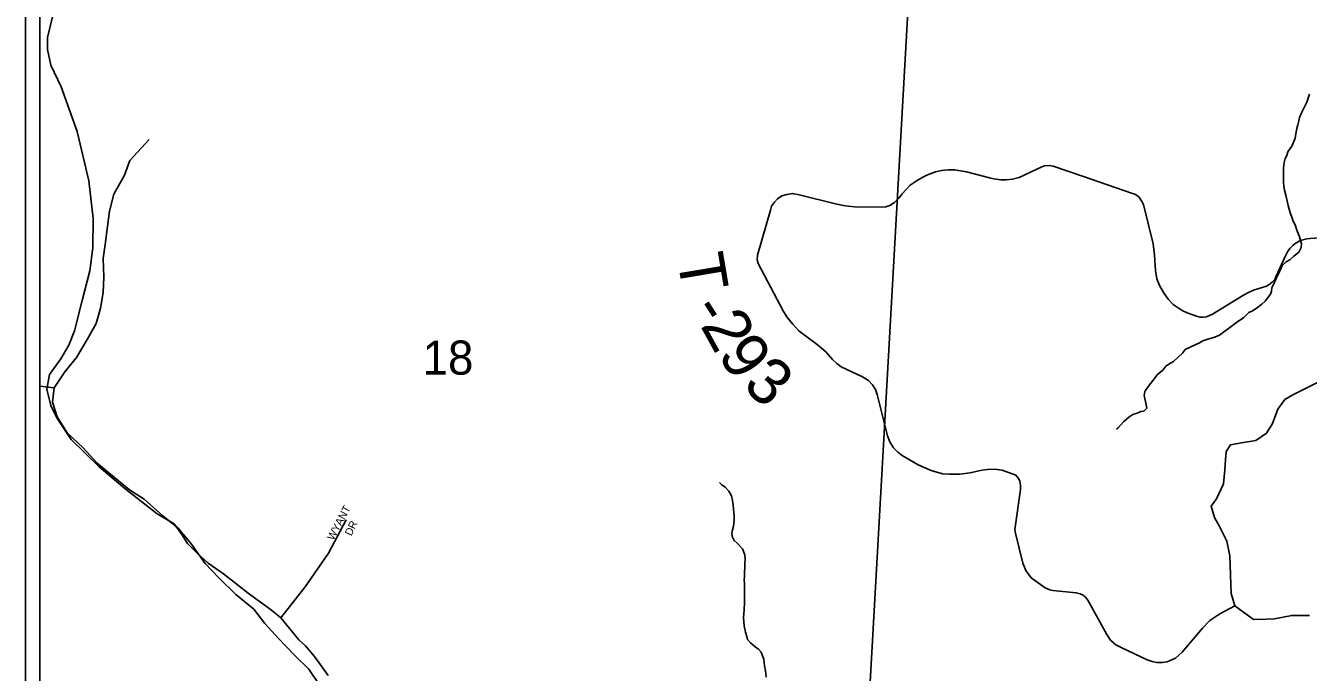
# Model space of a CAD drawing. Extents: x 0 to 34, y 0 to 22.
# Drawn here: x 2.6 to 4.174, y 18.251 to 19.045 of the extents above; entities that cross this region are included whole.
import ezdxf

# ---------------------------------------------------------------- set-up
doc = ezdxf.new("R2010")
doc.units = 0
for name, color, linetype in [('GM_X_County', 7, 'Continuous'), ('GM_X_County_Road', 7, 'Continuous'), ('GM_X_Minor_River', 7, 'Continuous'), ('GM_X_Section', 7, 'Continuous'), ('GM_X_Section_Text', 7, 'Continuous'), ('GM_X_Township', 7, 'Continuous'), ('GM_X_Township_Road', 7, 'Continuous'), ('GM_X_Township_Road_Text', 7, 'Continuous'), ('GM_X_Township_ROW', 7, 'Continuous'), ('GM_X_Township_Subdivision', 7, 'Continuous'), ('GM_X_Township_Subdivision_Text', 7, 'Continuous'), ('SH_Data', 7, 'Continuous')]:
    doc.layers.add(name, color=color, linetype=linetype)

msp = doc.modelspace()

# ---------------------------------------------------------------- linework, layer by layer
at = {"layer": 'GM_X_County'}
msp.add_lwpolyline([(9.4175, 16.6203), (9.4175, 20.9), (2.6175, 20.9), (2.6175, 15.1694)], dxfattribs=at)
at = {"layer": 'GM_X_County_Road'}
for points in [[(2.9713, 18.2478), (2.9542, 18.2709), (2.9432, 18.2841), (2.9352, 18.2913), (2.9132, 18.3182), (2.9014, 18.3277), (2.8729, 18.3485), (2.8429, 18.3723), (2.8239, 18.3856), (2.8095, 18.3984), (2.7985, 18.4098), (2.7916, 18.4208), (2.7821, 18.4337), (2.7612, 18.4461), (2.7217, 18.4772), (2.6902, 18.5036), (2.656, 18.5373), (2.6381, 18.5639), (2.6309, 18.579), (2.6259, 18.5991), (2.6293, 18.6169), (2.6433, 18.6363), (2.6531, 18.653), (2.6599, 18.6705), (2.6692, 18.7077), (2.6786, 18.7441), (2.6824, 18.7726), (2.683, 18.8086), (2.6776, 18.8545), (2.6631, 18.9152), (2.6436, 18.9698), (2.6307, 18.9967), (2.6268, 19.0157), (2.6268, 19.0305), (2.6362, 19.0696)], [(4.1752, 18.3214), (4.1686, 18.3214), (4.1533, 18.3214), (4.1322, 18.3173), (4.1222, 18.3168), (4.1065, 18.3165), (4.0833, 18.3329), (4.0791, 18.3484), (4.0779, 18.3712), (4.0774, 18.3944), (4.0736, 18.4126), (4.0641, 18.4311), (4.0584, 18.4414), (4.0542, 18.4554), (4.061, 18.4645), (4.0696, 18.4828), (4.0711, 18.4998), (4.0718, 18.5124), (4.0726, 18.5226), (4.0779, 18.5306), (4.0915, 18.5333), (4.1093, 18.536), (4.1222, 18.5451), (4.1297, 18.5569), (4.1361, 18.5743), (4.1448, 18.5865), (4.1547, 18.5922), (4.1872, 18.6082)]]:
    msp.add_lwpolyline(points, dxfattribs=at)
at = {"layer": 'GM_X_Minor_River'}
for points in [[(4.1752, 18.9609), (4.1716, 18.951), (4.1697, 18.9469), (4.1657, 18.939), (4.1626, 18.9322), (4.1618, 18.9284), (4.1606, 18.9235), (4.1593, 18.919), (4.1585, 18.9148), (4.1576, 18.9072), (4.1537, 18.8982), (4.1513, 18.8944), (4.1486, 18.8903), (4.1474, 18.8858), (4.145, 18.882), (4.1438, 18.8771), (4.1433, 18.8706), (4.143, 18.8536), (4.1437, 18.8475), (4.1444, 18.8433), (4.1465, 18.8356), (4.149, 18.8242), (4.1514, 18.8154), (4.1529, 18.8112), (4.1551, 18.8051), (4.1576, 18.8005), (4.1594, 18.794), (4.1627, 18.786), (4.1641, 18.7814), (4.1652, 18.7776), (4.1647, 18.7727), (4.162, 18.767), (4.1558, 18.7622), (4.1508, 18.7577), (4.1462, 18.7551), (4.1416, 18.7507), (4.1392, 18.745), (4.1365, 18.7397), (4.1341, 18.7348), (4.1313, 18.7281), (4.129, 18.7235), (4.1285, 18.7194), (4.127, 18.7156), (4.1207, 18.707), (4.1165, 18.7032), (4.1096, 18.6981), (4.105, 18.6951), (4.1004, 18.6929), (4.0943, 18.6869), (4.0854, 18.681), (4.0774, 18.6747), (4.0712, 18.6702), (4.0647, 18.6654), (4.059, 18.6628), (4.0514, 18.6607), (4.0441, 18.6582), (4.0399, 18.6559), (4.0288, 18.6504), (4.0224, 18.6475), (4.0196, 18.6434), (4.0081, 18.6329), (4.0043, 18.6307), (3.9989, 18.6274), (3.995, 18.6225), (3.9885, 18.617), (3.9834, 18.6102), (3.9776, 18.6027), (3.973, 18.596), (3.9721, 18.5914), (3.9732, 18.5876)], [(2.7514, 18.9055), (2.7279, 18.8798), (2.7211, 18.8616), (2.7081, 18.8381), (2.7028, 18.8176), (2.7005, 18.7986), (2.6974, 18.7766), (2.6951, 18.7592), (2.6959, 18.7364), (2.6951, 18.7175), (2.692, 18.6985), (2.6867, 18.6795), (2.6753, 18.6598), (2.6624, 18.6378), (2.648, 18.6204), (2.6351, 18.6007), (2.6328, 18.5832), (2.6388, 18.565), (2.6509, 18.5453), (2.6706, 18.5271), (2.6879, 18.5081), (2.7091, 18.4906), (2.7272, 18.4754), (2.7454, 18.464), (2.7681, 18.4435), (2.787, 18.4284), (2.8036, 18.4086), (2.8202, 18.3851), (2.8368, 18.3676), (2.858, 18.3471), (2.8799, 18.3289), (2.8935, 18.3114), (2.9101, 18.2932), (2.9298, 18.2727), (2.9472, 18.2553), (2.9593, 18.2378)], [(2.6175, 18.6026), (2.6351, 18.6007), (2.6342, 18.6007)], [(3.9732, 18.5876), (3.9739, 18.5838), (3.9746, 18.5796), (3.9753, 18.5758), (3.9718, 18.572), (3.968, 18.5714), (3.9634, 18.5695), (3.9584, 18.5677), (3.9535, 18.5648), (3.9469, 18.5588), (3.9404, 18.5517), (3.9381, 18.5501)], [(3.4815, 18.3283), (3.4817, 18.337), (3.4818, 18.3438), (3.4819, 18.3526), (3.4817, 18.3602), (3.4814, 18.3651), (3.4819, 18.3689), (3.4821, 18.3856), (3.4826, 18.3905), (3.4823, 18.3958), (3.4794, 18.4031), (3.4727, 18.4101), (3.469, 18.4132), (3.4668, 18.4181), (3.4665, 18.4223), (3.4673, 18.4265), (3.4682, 18.431), (3.4691, 18.4386), (3.4692, 18.4435), (3.4688, 18.4473), (3.4679, 18.4572), (3.4672, 18.4622), (3.4658, 18.4679), (3.4625, 18.474), (3.458, 18.4787), (3.4539, 18.4814), (3.4511, 18.4846)], [(3.5085, 18.2454), (3.5075, 18.2538), (3.5064, 18.2595), (3.5054, 18.2675), (3.504, 18.2717), (3.5022, 18.2763), (3.4992, 18.2801), (3.4951, 18.2828), (3.4891, 18.2875), (3.4854, 18.2917), (3.4847, 18.2955), (3.4829, 18.3009), (3.4815, 18.3085), (3.4806, 18.3188), (3.4815, 18.3283)]]:
    msp.add_lwpolyline(points, dxfattribs=at)
at = {"layer": 'GM_X_Section'}
msp.add_line((2.6175, 19.1938), (2.6175, 18.1627), dxfattribs=at)
msp.add_lwpolyline([(2.6175, 18.1627), (3.6288, 18.1086), (3.6864, 19.1354), (2.6175, 19.1938)], dxfattribs=at)
msp.add_lwpolyline([(3.6864, 19.1354), (4.7704, 19.0729), (4.7124, 18.0487), (3.6288, 18.1086)], close=True, dxfattribs=at)
at = {"layer": 'GM_X_Township'}
msp.add_line((2.6175, 19.3567), (2.6175, 15.1694), dxfattribs=at)
at = {"layer": 'GM_X_Township_Road'}
for points in [[(4.0833, 18.3329), (4.0652, 18.3233), (4.0529, 18.3149), (4.0438, 18.3059), (4.0188, 18.2762), (4.0105, 18.2689), (4.0003, 18.2645), (3.9948, 18.2637), (3.9877, 18.2635), (3.9819, 18.2646), (3.976, 18.2667), (3.9438, 18.2818), (3.9374, 18.2852), (3.9308, 18.2911), (3.9264, 18.2978), (3.9031, 18.34), (3.9002, 18.3438), (3.8974, 18.3461), (3.8938, 18.3479), (3.8889, 18.3492), (3.8603, 18.3519), (3.8563, 18.3526), (3.8506, 18.3553), (3.8337, 18.3675), (3.8269, 18.3764), (3.8234, 18.3856), (3.8143, 18.4223), (3.8137, 18.4269), (3.8205, 18.476), (3.8205, 18.4813), (3.8195, 18.4859), (3.8183, 18.4889), (3.8146, 18.4933), (3.7981, 18.4996), (3.7885, 18.501), (3.7801, 18.5006), (3.7732, 18.4997), (3.7586, 18.4962), (3.746, 18.4945), (3.7332, 18.4947), (3.7248, 18.4952), (3.7109, 18.4991), (3.6951, 18.5063), (3.6755, 18.5177), (3.6701, 18.5216), (3.6645, 18.527), (3.66, 18.5342), (3.6573, 18.5418), (3.6447, 18.5923), (3.6425, 18.5985), (3.6389, 18.6045), (3.6338, 18.6096), (3.6267, 18.6141), (3.6005, 18.6265), (3.5951, 18.6305), (3.5899, 18.6354), (3.5817, 18.6447), (3.5712, 18.654), (3.5568, 18.6645), (3.5484, 18.6706), (3.541, 18.6786), (3.5346, 18.6867), (3.5298, 18.6944), (3.4987, 18.753), (3.4973, 18.7579), (3.4977, 18.7636), (3.5136, 18.8185), (3.5152, 18.8237), (3.5185, 18.8285), (3.5225, 18.8326), (3.5278, 18.8361), (3.534, 18.8379), (3.5407, 18.839), (3.5421, 18.8387), (3.5473, 18.8379), (3.5953, 18.826), (3.6055, 18.8238), (3.6169, 18.8227), (3.6505, 18.8224), (3.6551, 18.8226), (3.6602, 18.8242), (3.6659, 18.8279), (3.6715, 18.8336), (3.6753, 18.8387), (3.6801, 18.8442), (3.685, 18.8495), (3.6936, 18.8552), (3.7007, 18.8591), (3.7065, 18.8622), (3.716, 18.8657), (3.7235, 18.8673), (3.7317, 18.8682), (3.7396, 18.8682), (3.7544, 18.8657), (3.7823, 18.8582), (3.7876, 18.8569), (3.7962, 18.8558), (3.8027, 18.8557), (3.8105, 18.8566), (3.8189, 18.8586), (3.8466, 18.8717), (3.85, 18.8732), (3.8557, 18.8736), (3.8606, 18.8727), (3.8965, 18.8603)], [(4.1517, 18.7725), (4.1545, 18.7752), (4.1576, 18.7777), (4.1625, 18.7806), (4.1667, 18.7823), (4.1719, 18.7835), (4.1757, 18.784), (4.3179, 18.7937)]]:
    msp.add_lwpolyline(points, dxfattribs=at)
at = {"layer": 'GM_X_Township_ROW'}
msp.add_lwpolyline([(3.8965, 18.8603), (3.8967, 18.8603), (3.9577, 18.8393), (3.9614, 18.8379), (3.9661, 18.8345), (3.9694, 18.8294), (3.9712, 18.8255), (3.9831, 18.7773), (3.9849, 18.7635), (3.9862, 18.7446), (3.9878, 18.7345), (3.9912, 18.7253), (3.9966, 18.7163), (4.0017, 18.7095), (4.0079, 18.7028), (4.0138, 18.6986), (4.0163, 18.697), (4.0186, 18.6956), (4.025, 18.6928), (4.0362, 18.6887), (4.041, 18.6875), (4.0446, 18.6874), (4.0487, 18.6879), (4.0531, 18.6896), (4.0561, 18.6912), (4.0942, 18.7142), (4.1002, 18.7177), (4.1065, 18.7203), (4.1117, 18.7222), (4.1222, 18.7255), (4.1256, 18.7273), (4.1294, 18.7303), (4.1323, 18.7335), (4.1338, 18.7369), (4.1454, 18.7628), (4.148, 18.7676), (4.1507, 18.7717), (4.1509, 18.7718), (4.1517, 18.7725)], dxfattribs=at)
at = {"layer": 'GM_X_Township_Subdivision'}
msp.add_lwpolyline([(2.9132, 18.3182), (2.943, 18.3566), (2.9717, 18.3976), (2.9932, 18.4387)], dxfattribs=at)
at = {"layer": 'SH_Data'}
msp.add_line((2.6, 20.9), (2.6, 14.1), dxfattribs=at)

# ---------------------------------------------------------------- texts
at = {"layer": 'GM_X_Section_Text'}
msp.add_text('18', height=0.04186, rotation=0, dxfattribs=at).set_placement((3.087, 18.6168))
at = {"layer": 'GM_X_Township_Road_Text'}
for s, rotation, p in [('T', 279.5366, (3.399, 18.7609)), ('2', 299.0258, (3.4271, 18.6771)), ('-', 302.5969, (3.415, 18.6959)), ('9', 305.4475, (3.4478, 18.6406)), ('3', 319.1053, (3.478, 18.6012))]:
    msp.add_text(s, height=0.0568, rotation=rotation, dxfattribs=at).set_placement(p)
at = {"layer": 'GM_X_Township_Subdivision_Text'}
for s, rotation, p in [('WYANT', 61.9252, (2.9776, 18.4126)), ('DR', 64.8001, (2.9996, 18.4182))]:
    msp.add_text(s, height=0.00947, rotation=rotation, dxfattribs=at).set_placement(p)

doc.saveas('drawing.dxf')
